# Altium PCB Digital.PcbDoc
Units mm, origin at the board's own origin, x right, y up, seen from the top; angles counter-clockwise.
Board outline 110.7 x 78 mm, 4 copper layers (Top Layer, GND, VCC, Bottom Layer), stack 0.603 mm thick; 50 components, 27 nets, 273 pads, 175 vias.
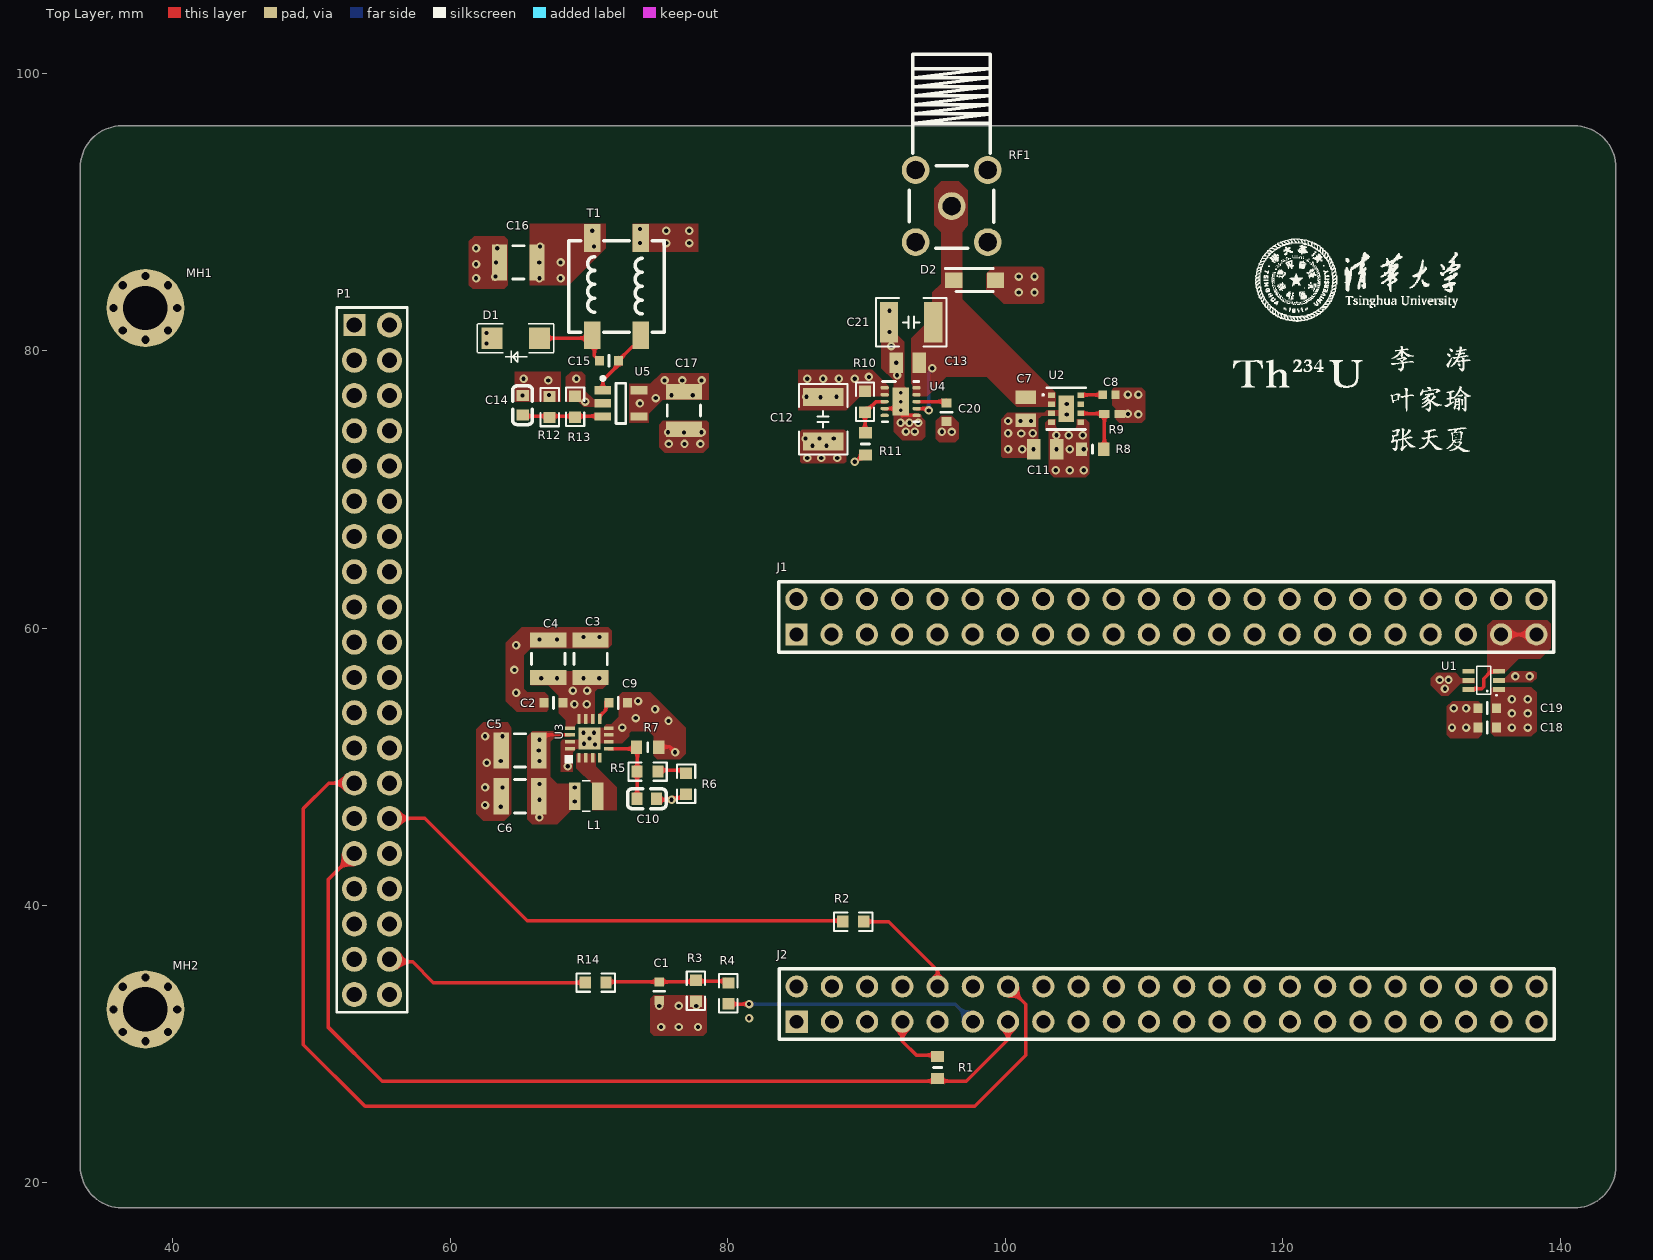
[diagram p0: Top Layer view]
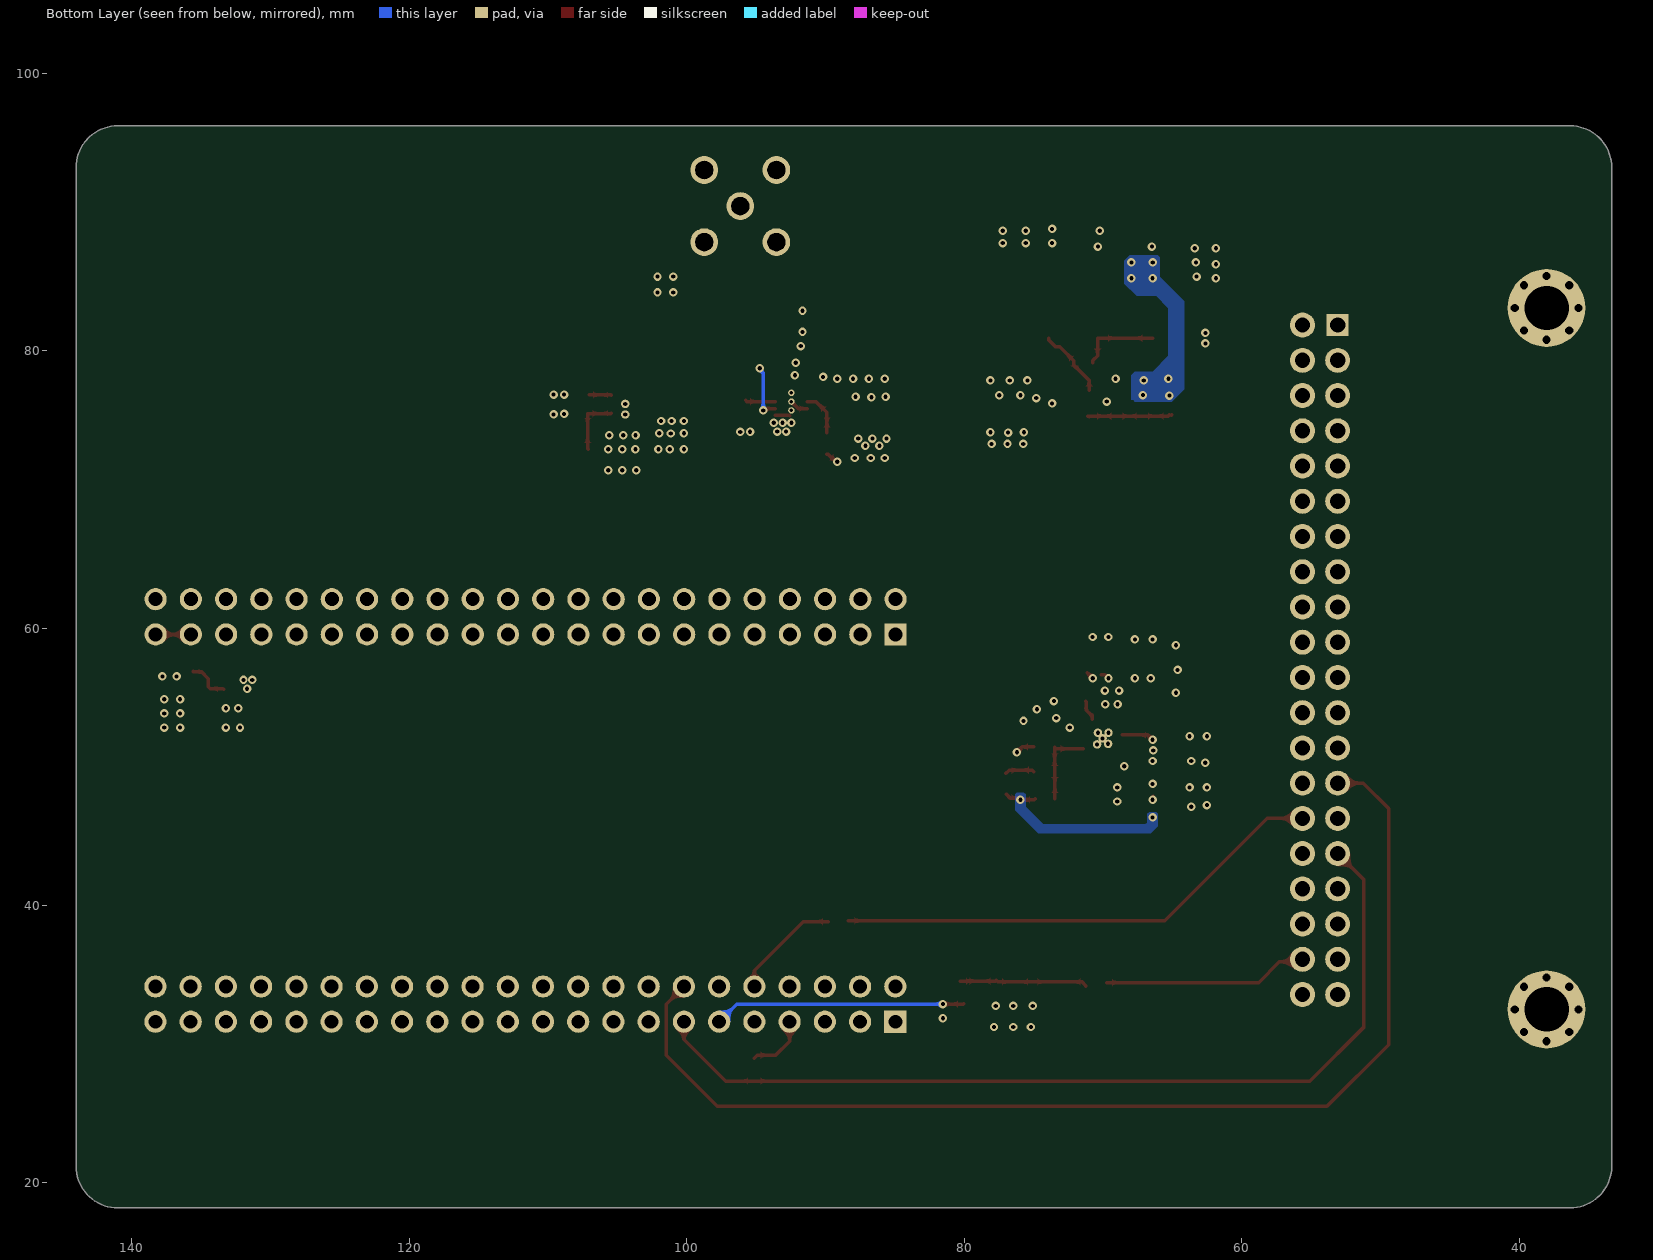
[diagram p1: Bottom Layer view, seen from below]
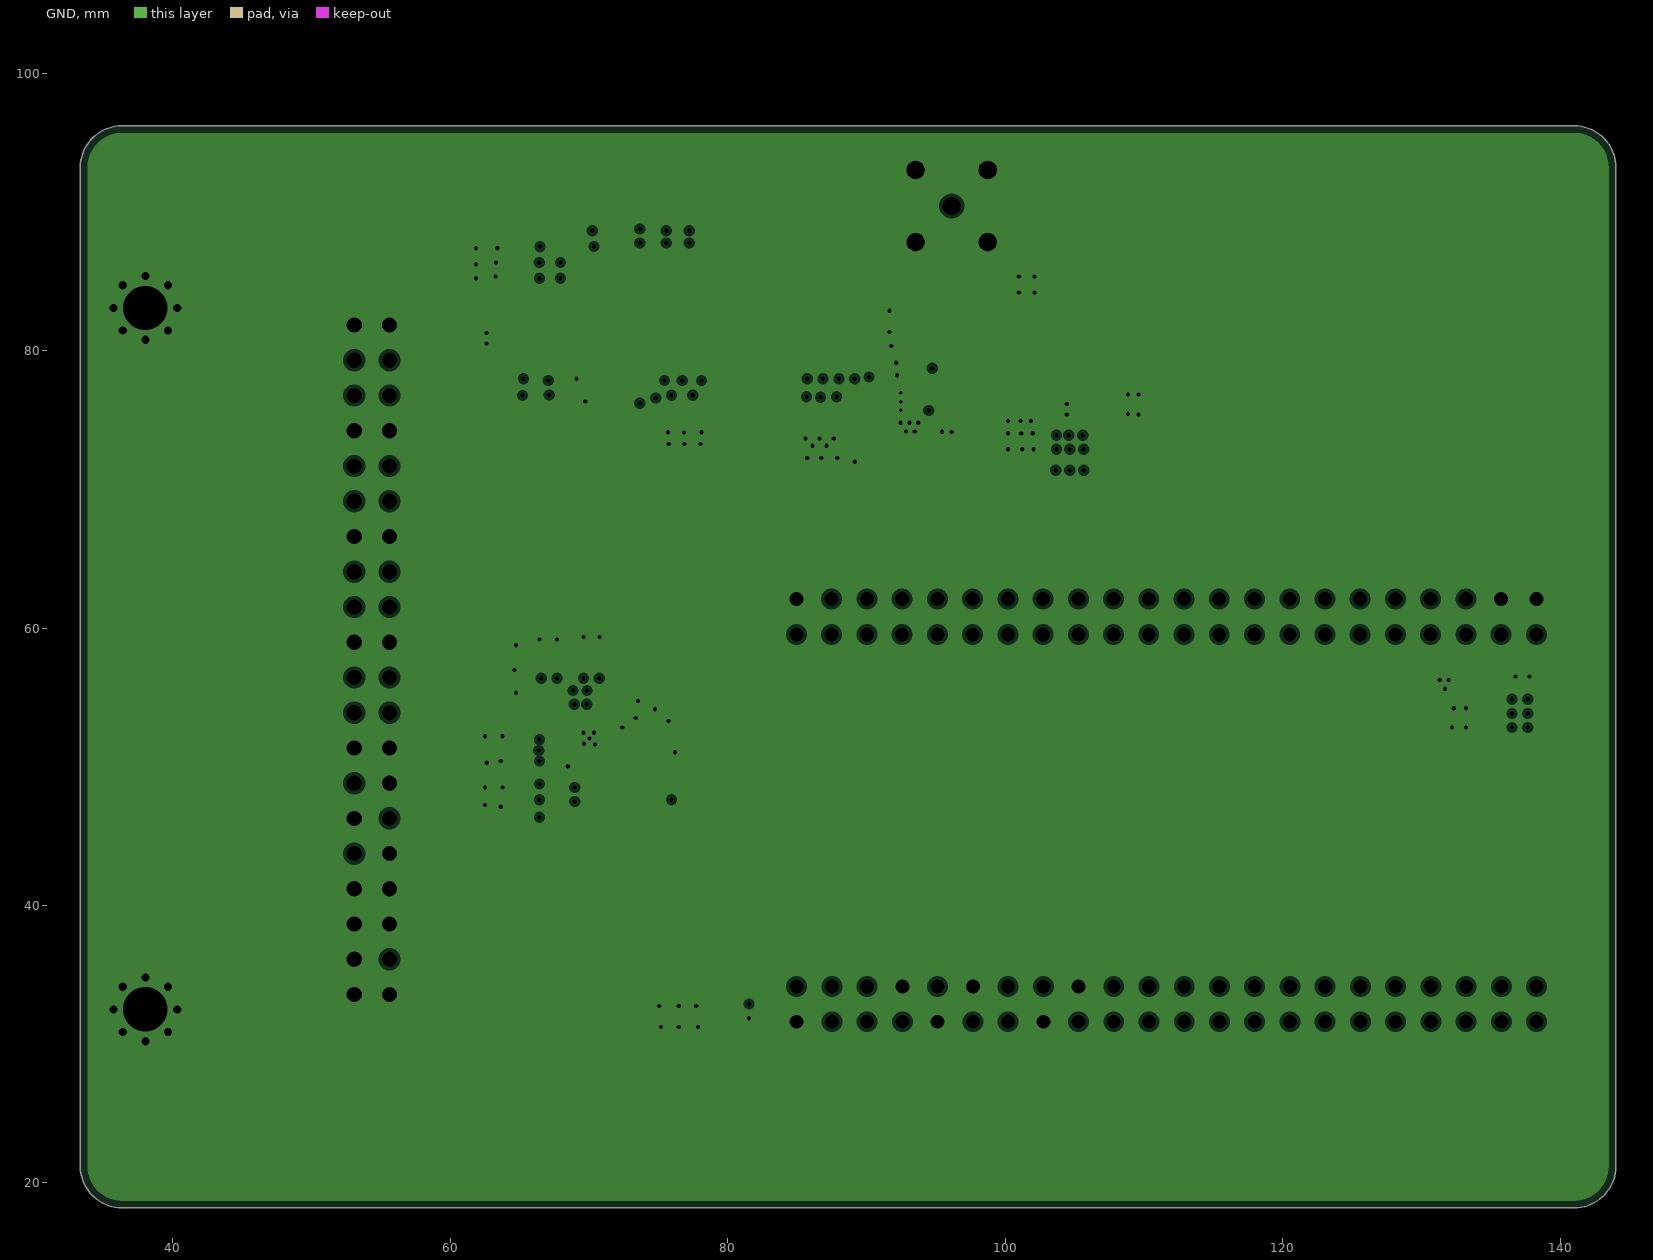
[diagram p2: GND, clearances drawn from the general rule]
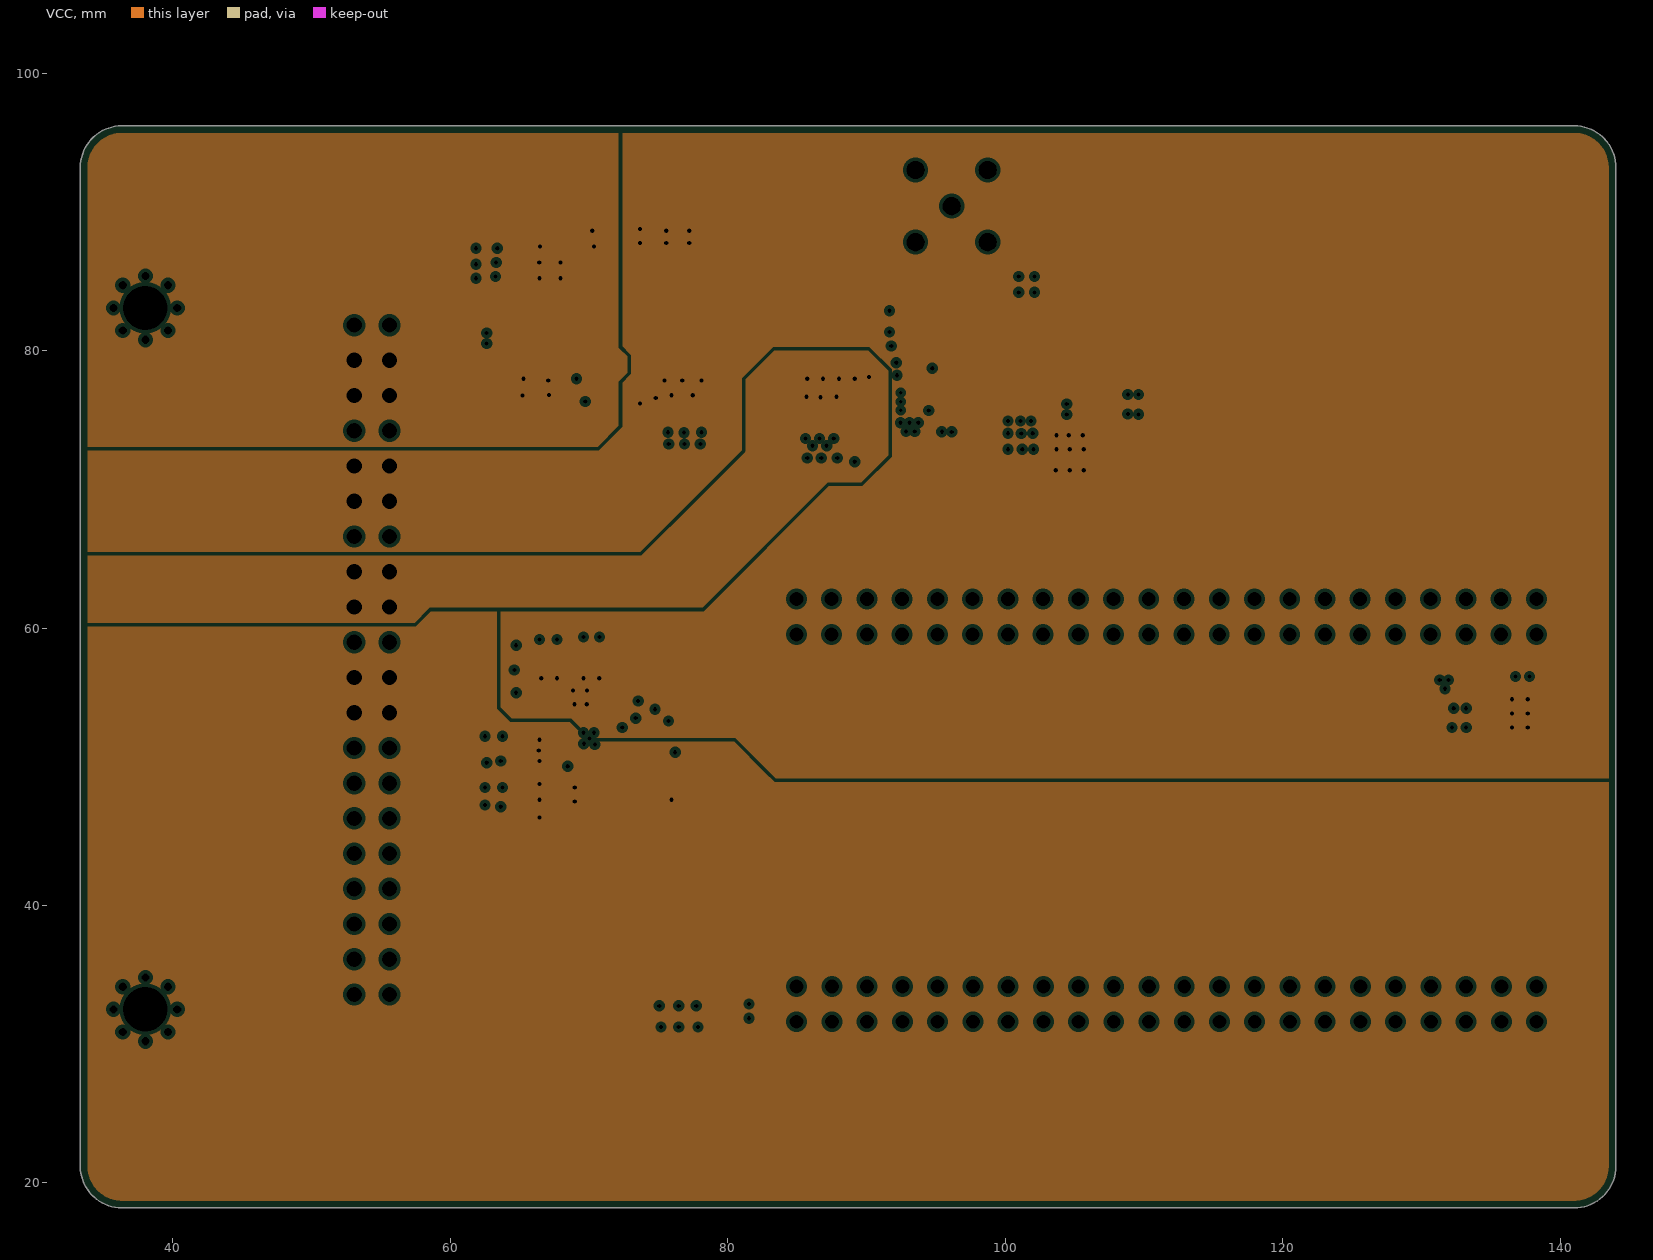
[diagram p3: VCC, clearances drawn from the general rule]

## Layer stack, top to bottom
Top Solder: solder mask 0.0102, Solder Resist, Dk 3.5
Top Layer: signal copper 0.0356
Dielectric 1: dielectric 0.32, FR-4, Dk 4.8
GND: plane copper 0.035, net GND
Dielectric 2: prepreg 0.0711, PP-006, Dk 4.1
VCC: plane copper 0.035, net (Multiple Nets)
Dielectric 3: prepreg 0.0711, PP-006, Dk 4.1
Bottom Layer: signal copper 0.0356
Bottom Solder: solder mask 0.0102, Solder Resist, Dk 3.5

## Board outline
33.322,21.209 33.322,93.209 cw(c36.322,93.209) 36.322,96.209 141.018,96.209 cw(c141.018,93.209) 144.018,93.209 144.018,21.209 cw(c141.018,21.209) 141.018,18.209 36.322,18.209 cw(c36.322,21.209)

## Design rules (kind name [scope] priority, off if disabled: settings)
Clearance [All] p1: gap=0.152 ignorepadtopadclearanceinfootprint=TRUE except(0: Arc-Hole Track-Hole SMDPad-Hole THPad-Hole Via-Hole Fill-Hole Poly-Hole Region-Hole Text-Hole)
HoleSize [All] p1: absolutevalues=TRUE maxlimit=100 minlimit=0.025 maxpercent=80.000 minpercent=20.000
HoleToHoleClearance [All] p1: gap=0 allowstackedmicrovias=TRUE
MinimumSolderMaskSliver [All] p1 off: minsoldermaskwidth=0
PlaneClearance [All] p1: clearance=0.254
PlaneConnect [All] p1: planeconnectstyle=Direct reliefexpansion=0.508 reliefentries=4 reliefconductorwidth=0.254 reliefairgap=0.254
PolygonConnect [All] p1: connectstyle=Direct reliefconductorwidth=0.254 reliefentries=4 polygonreliefangle="90 Angle" airgapwidth=0.254
RoutingVias [All] p1: holewidth=0.305 width=0.61 viastyle="Through Hole" minholewidth=0 minwidth=0 maxholewidth=100 maxwidth=100
SilkToSilkClearance [All] p1 off: silktosilkclearance=0
SilkToSolderMaskClearance [IsPad] p1 off: minsilkscreentomaskgap=0 clearancetoexposedcopper=TRUE
SolderMaskExpansion [All] p1: expansion=0.102 istentingtop=FALSE
Width [All] p1: maxlimit=0.508 minlimit=0.152 preferedwidth=0.254
23 further rules are at their usual default settings.

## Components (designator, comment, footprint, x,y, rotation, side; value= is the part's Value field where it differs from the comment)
C1 "100nF/100V" GRM18x 75.057,33.821 r270 top
C2 "100nF/100V" GRM18x 67.437,54.61 r180 top
C3 "22uF" C1210 70.104,57.785 r270 top
C4 "22uF" C1210 67.056,57.785 r270 top
C5 "22uF" C1210 65.024,51.181 r0 top
C6 "22uF" C1210 65.024,47.879 r0 top
C7 "10uF/25V" CAPC2012X145N 101.473,75.819 r90 top
C8 "3.3nF/50V" CAPC1005X70N 107.49,76.835 r180 top
C9 "10nF/50V" GRM18x 72.096,54.61 r180 top
C10 "1nF" C0603 74.168,47.625 r0 top
C11 "22uF/10V" CAPC2012X145N 102.87,72.898 r0 top
C12 "10uF 50V" C1210-H2r50 86.868,75.057 r90 top
C13 "1uF 100V" CAPC2012X145N 92.964,79.121 r0 top
C14 "220pF" C0603 65.278,76.073 r90 top
C15 "1uF/25V" GRM18x 71.436,79.273 r0 top
C16 "22uF" C1210 64.897,86.36 r0 top
C17 "4.7uF" C1210 76.835,75.692 r90 top
C18 "1uF/25V" GRM18x 134.747,52.832 r180 top
C19 "100nF/100V" GRM18x 134.747,54.229 r180 top
C20 "1uF/25V" GRM18x 95.758,75.565 r90 top
C21 "10uF 50V" C1210-H2r50 93.218,82.042 r0 top
D1 "MBR0520" 1206_Diode 66.421,80.899 r180 top
D2 "TVS/13V" SODFL3616X98N 97.79,85.09 r0 top
J1 "Header_2x22_Female_P2.54" HDR-TH_44P-P2.54-V-F-R2-C22-S2.54 111.617,60.814 r0 top
J2 "Header_2x22_Female_P2.54" HDR-TH_44P-P2.54-V-F-R2-C22-S2.54 111.633,32.893 r0 top
L1 "2.2uH" L1008 69.8,48.073 r180 top
MH1 "Mounting Hole (Screw)" MOUNT_PAD_L 38.015,83.078 r0 top
MH2 "Mounting Hole (Screw)" MOUNT_PAD_L 38.016,32.511 r0 top
P1 "Header_2x20_male_P2.54" 2541WV-2x20P 54.345,57.712 r270 top
R1 "100Ω" RESC1608X55N 95.123,28.321 r270 top
R2 "22Ω" R0603 89.027,38.862 r180 top
R3 "1kΩ" R0603 77.724,33.87 r90 top
R4 "9.1kΩ" R0603 80.01,33.655 r270 top
R5 "301kΩ" R0603 74.224,49.633 r0 top
R6 "11.5kΩ" R0603 76.962,48.768 r270 top
R7 "100kΩ" RESC1608X55N 74.224,51.411 r180 top
R8 "60kΩ" RESC1608X55N 106.299,72.898 r180 top
R9 "12kΩ" RESC1005X35N 107.696,75.438 r180 top
R10 "10.5kΩ" R0603 89.916,76.327 r90 top
R11 "2kΩ" RESC1608X55N 89.916,73.279 r90 top
R12 "29.4kΩ" R0603 67.183,75.946 r90 top
R13 "10kΩ" R0603 68.961,75.946 r270 top
R14 "0Ω" R0603 70.485,34.417 r0 top
RF1 "HJ-SMA508" HJ-SMA508 100.776,93.277 r270 top
T1 "CLS62NP-100NC" SMD-4P,6.8x6.6mm 71.755,84.582 r90 top
U1 "lm66100dckr_c2869734" SC-70-6_L2.0-W1.3-P0.65-LS2.1-BL 134.493,56.234 r90 top
U2 "TPS82130SILR" SIL0008D 104.394,75.819 r0 top
U3 "TPS62130RGT" QFN16 70.021,52.046 r90 top
U4 "TPS7A90" DSK0010A 92.456,76.327 r0 top value=Value
U5 "LT1931" SOT23-5 72.293,76.2 r0 top value=Value

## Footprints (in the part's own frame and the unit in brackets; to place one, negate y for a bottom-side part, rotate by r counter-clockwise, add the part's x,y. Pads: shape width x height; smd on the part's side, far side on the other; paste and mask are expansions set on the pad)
1206_Diode [mil] "1206_Diode"
  rect 60x60 smd: 1(0,0) 2(135,0)
  silkscreen extent -41,-41 176,70, body extent -11,-34 141,33, height 56
2541WV-2x20P [mil]
  rect 62x62 hole 43.3: 1(-950,-50)
  round 70.9 hole 43.3: 2(-950,50) 3(-850,-50) 4(-850,50) 5(-750,-50) 6(-750,50) 7(-650,-50) 8(-650,50) 9(-550,-50) 10(-550,50) 11(-450,-50) 12(-450,50) 13(-350,-50) 14(-350,50) 15(-250,-50) 16(-250,50) 17(-150,-50) 18(-150,50) 19(-50,-50) 20(-50,50) 21(50,-50) 22(50,50) 23(150,-50) 24(150,50) 25(250,-50) 26(250,50) 27(350,-50) 28(350,50) 29(450,-50) 30(450,50) 31(550,-50) 32(550,50) 33(650,-50) 34(650,50) 35(750,-50) 36(750,50) 37(850,-50) 38(850,50) 39(950,-50) 40(950,50)
  silkscreen extent -1000,-100 1000,100
C0603 [mm]
  rect 0.8x0.9 smd paste+0.051: 1(-0.707,0.075) 2(0.693,0.075)
  silkscreen extent -1.4,-0.64 1.38,0.79
C1210 [mm] "Chip Capacitor, Body 3.2x2.5mm, IPC High Density"
  rect 1.1x2.6 smd: 1(-1.35,0) 2(1.35,0)
  silkscreen extent -0.4,-1.2 0.4,1.2, body extent -1.7,-1.35 1.7,1.35, height 1.3
C1210-H2r50 [mm]
  rect 1.321x2.921 smd paste+0 mask+0.076: 1(-1.6,0) 2(1.6,0)
  silkscreen extent -2.55,-1.75 2.55,1.75, body extent -1.6,-1.27 1.6,1.23, height 2.6
CAPC1005X70N [mm]
  rect 0.6x0.62 smd: 1(-0.46,0) 2(0.46,0)
  body extent -0.5,-0.25 0.5,0.25, height 0.5
CAPC2012X145N [mm]
  rect 0.97x1.47 smd: 1(-0.83,0) 2(0.83,0)
  body extent -1,-0.63 1,0.63, height 1.45
DSK0010A [mm]
  oval 0.6x0.25 smd paste+0 mask+0: 1(-1.15,1) 2(-1.15,0.5) 3(-1.15,0) 4(-1.15,-0.5) 5(-1.15,-1) 6(1.15,-1) 7(1.15,-0.5) 8(1.15,0) 9(1.15,0.5) 10(1.15,1)
  round 0.457 hole 0.254: 11(0,-0.635) 11(0,0) 11(0,0.635)
  rect 1.2x2 smd paste-0.6 mask+0: 11(0,0)
  silkscreen extent -1.3,-1.45 1.3,1.45
GRM18x [mm]
  rect 0.65x0.7 smd: 1(-0.675,0) 2(0.675,0)
  silkscreen extent 0,-0.4 0,0.4, body extent -0.8,-0.45 0.8,0.45, height 0.8
HDR-TH_44P-P2.54-V-F-R2-C22-S2.54 [mil]
  rect 63x63 hole 39.4: 1(-1050,-50)
  round 63 hole 39.4: 2(-1050,50) 3(-950,-50) 4(-950,50) 5(-850,-50) 6(-850,50) 7(-750,-50) 8(-750,50) 9(-650,-50) 10(-650,50) 11(-550,-50) 12(-550,50) 13(-450,-50) 14(-450,50) 15(-350,-50) 16(-350,50) 17(-250,-50) 18(-250,50) 19(-150,-50) 20(-150,50) 21(-50,-50) 22(-50,50) 23(50,-50) 24(50,50) 25(150,-50) 26(150,50) 27(250,-50) 28(250,50) 29(350,-50) 30(350,50) 31(450,-50) 32(450,50) 33(550,-50) 34(550,50) 35(650,-50) 36(650,50) 37(750,-50) 38(750,50) 39(850,-50) 40(850,50) 41(950,-50) 42(950,50) 43(1050,-50) 44(1050,50)
  silkscreen extent -1100,-100 1100,100
HJ-SMA508 [mm]
  round 2 hole 1.3 slot 1.305 at 0 deg paste-2539.97 mask+0.051: 1(2.853,-4.637) 2(0.253,-2.037) 3(0.253,-7.237) 4(5.453,-7.237) 5(5.453,-2.037)
  silkscreen extent -8.1,-7.69 5.9,-1.59
L1008 [mm]
  rect 0.85x2 smd: 1(-0.821,0.194) 2(0.839,0.194)
  silkscreen extent -0.28,-0.91 0.3,1.29
MOUNT_PAD_L [mm]
  round 5.6 hole 3.2: 1(0,0)
QFN16 [mm]
  rect 1.6x1.6 smd: 0(0,0)
  rect 0.7x0.25 smd: 1(-1.4,0.75) 2(-1.4,0.25) 3(-1.4,-0.25) 4(-1.4,-0.75) 9(1.4,-0.75) 10(1.4,-0.25) 11(1.4,0.25) 12(1.4,0.75)
  rect 0.25x0.7 smd: 5(-0.75,-1.4) 6(-0.25,-1.4) 7(0.25,-1.4) 8(0.75,-1.4) 13(0.75,1.4) 14(0.25,1.4) 15(-0.25,1.4) 16(-0.75,1.4)
  silkscreen extent -1.8,1.2 -1.2,1.8, body extent -1.5,-1.5 1.5,1.5, height 0.9
R0603 [mm]
  rect 0.806x0.864 smd paste-100 mask+0.051: 1(-0.765,0.026) 2(0.741,0.026)
  silkscreen extent -1.4,-0.64 1.37,0.69
RESC1005X35N [mm]
  rect 0.75x0.6 smd: 1(-0.55,0) 2(0.55,0)
  body extent -0.5,-0.25 0.5,0.25, height 0.35
RESC1608X55N [mm]
  rect 0.8x0.95 smd: 1(-0.8,0) 2(0.8,0)
  silkscreen extent 0,-0.3 0,0.3, body extent -0.8,-0.4 0.8,0.4, height 0.55
SC-70-6_L2.0-W1.3-P0.65-LS2.1-BL [mil]
  rect 13.8x33.5 smd paste+0 mask+2: 1(-25.6,-43.3) 2(0,-43.3) 3(25.6,-43.3) 4(25.6,43.3) 5(0,43.3) 6(-25.6,43.3)
  silkscreen extent -44,-38 39,20
SIL0008D [mm]
  rect 0.5x0.4 smd: 1(-1.05,0.975) 2(-1.05,0.325) 3(-1.05,-0.325) 4(-1.05,-0.975) 5(1.05,-0.975) 6(1.05,-0.325) 7(1.05,0.325) 8(1.05,0.975)
  rect 1.1x1.9 smd: 9(0,0)
  silkscreen extent -1.7,-1.5 1.4,1.5, body extent -1.4,-1.5 1.4,1.5, height 1.31
SMD-4P,6.8x6.6mm [mm]
  rect 2x1.2 smd paste+0 mask+0.05: 1(-3.468,1.532) 2(-3.468,-1.968) 3(3.532,-1.968) 4(3.532,1.532)
  silkscreen extent -3.27,-3.65 3.33,3.21
SODFL3616X98N [mm]
  rect 1.24x1.12 smd: 1(-1.5,0) 2(1.5,0)
  silkscreen extent -2.12,-0.82 1.35,0.82, body extent -1.8,-0.82 1.8,0.82, height 0.98
SOT23-5 [mm] "SOT23, for LT1964, 5-Leads, Body 2.9x2.8mm (max), Pitch 0.95mm, IPC Medium Density"
  rect 1.2x0.6 smd: 1(-1.3,0.95) 2(-1.3,0) 3(-1.3,-0.95) 4(1.3,-0.95) 5(1.3,0.95)
  silkscreen extent -1.42,-1.45 0.35,1.92, body extent -1.37,-1.46 0.97,1.46, height 1

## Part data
C1 C2 C19: library part GCM188R72A104KA64D, "100nF 10% 100V X7R 0603", Arrow Part Number=GRM188Z71A106KA73D, Manufacturer_Name="Murata Electronics", Mouser Part Number=81-GRM188Z71A106KA3D
C3 C4 C5 C6 C16: library part GRM32ER71E226KE15L, "22uF ±10% 25V 1210 X7R"
C7: library part GCM21BC71E106KE36L, "10uF 10% 25V X7S 0805 汽车级", Arrow Part Number=GRM21BR72A103KA01L, Manufacturer_Name="Murata Electronics", Mouser Part Number=81-GRM21BR72A103K
C8: library part GRM1555C1H332JE01D, "3.3nF 5% 50V 0402 NP0", Manufacturer_Name="Murata Electronics", Manufacturer_Part_Number=GRM155C71H683KE19D, Mouser Part Number=81-GRM155C71H683KE9D
C9: library part GCM1885C1H103GA16D, "10nF 2% 50V 0603 C0G", Manufacturer_Name="Murata Electronics", Manufacturer_Part_Number=GRM155C71H683KE19D, Mouser Part Number=81-GRM155C71H683KE9D
C10: library part GRM188R71H102KA01D, "1nF ±10% 50V 0603 X7R"
C11: library part GRM21BZ71A226ME15L, "22uF 10% 10V X7R 0805", Arrow Part Number=GRM21BR72A103KA01L, Manufacturer_Name="Murata Electronics", Mouser Part Number=81-GRM21BR72A103K
C12 C21: library part GRM32ER71H106KA12L, "10uF 50V 10% 1210 X7R"
C13: library part GCM21BC72A105KE36L, "1uF 10% 100V X7S 0805", Arrow Part Number=GRM21BR72A103KA01L, Manufacturer_Name="Murata Electronics", Mouser Part Number=81-GRM21BR72A103K
C14: library part GCM1885C2A221FA16D, "220pF ±1% 100V 0603 C0G"
C15 C18 C20: library part GCM188R71E105KA64D, "1uF 10% 25V X7R 0603", Arrow Part Number=GRM188Z71A106KA73D, Manufacturer_Name="Murata Electronics", Mouser Part Number=81-GRM188Z71A106KA3D
C17: library part GRM32ER71H475KA88L, "4.7uF ±10% 50V X7R 1210"
D1: library part DIODE
D2: library part SMF13A, "TVS 工作电压13V 最大钳位电压21.5V 单向", Arrow Part Number=SMF26AT1G, Manufacturer_Name=LITTELFUSE
J1 J2: "插孔结构:2x22P;间距:2.54mm;行距:2.54mm;圆孔/方孔:方孔;安装方式:直插;排数:双排;总孔位数:44P;额定电流:3A;额定电压:-;插孔方向:顶部;塑高:8.5mm;触头材质:黄铜;触头镀层:金;工作温度:-40℃~+105℃;", Current Rating=3A, JLCPCB Part Class="Extended Part", LCSC Part Name="间距2.54mm 2x22Pin 直插 PC3.0 H8.5", Manufacturer=HC(虹成电子), ManufacturerPart=HC-PM254-8.5H-2x22PZ, Operating Temperature=-40℃~+105℃, Voltage Rating (Max)=-
L1: library part FXLB252012-2R2-M, "2.2uH ±20% 3.3A 1008"
MH1 MH2: library part Mounting-Hole-Screw_1, "Mounting Hole, M3 Screw"
P1: "插针结构:2x20P;间距:2.54mm;行距:2.54mm;圆针/方针:方针;安装方式:直插;排数:双排;总PIN位数:40P;额定电流:3A;配合针长度:6mm;塑高:2.54mm;端接针长度:3mm;触头材质:黄铜;触头镀层:金;工作温度:-55℃~+105℃;", Current Rating=3A, JLCPCB Part Class="Extended Part", LCSC Part Name="2x20P 间距:2.54mm 方针 直插", Manufacturer=HanElectricity(瀚源), ManufacturerPart=2541WV-2x20P, Operating Temperature=-55℃~+105℃
R1: library part SR0603FR-7T100RL, "100Ω 1% 0603 250mW 厚膜 耐浪涌", Manufacturer_Name=YAGEO, Manufacturer_Part_Number=RT0603BRD07523KL
R2: library part RT0603BRE0722RL, "薄膜电阻 22Ω ±0.1% 100mW 0603"
R3: library part RT0603BRE071KL, "薄膜电阻 1kΩ ±0.1% 100mW 0603"
R4: library part RT0603BRE079K1L, "薄膜电阻 9.1kΩ ±0.1% 100mW 0603"
R5: library part RT0603BRD07301KL, "薄膜电阻 301kΩ ±0.1% 100mW 0603"
R6: library part RT0603BRD0711K5L, "薄膜电阻 11.5kΩ ±0.1% 100mW 0603"
R7 R8: library part RT0603BRD07100KL, "100kΩ 0.1% 0603 100mW 薄膜 25ppm/℃", Manufacturer_Name=YAGEO, Manufacturer_Part_Number=RT0603BRD07523KL
R9: library part RT0402BRD0720KL, "20kΩ 0.1% 0402 62.5mW 薄膜 25ppm/℃", Manufacturer_Name=YAGEO, Manufacturer_Part_Number=RT0402BRD07100RL, Mouser Part Number=603-RT0402BRD07100RL
R10: library part RT0603BRD0710K5L, "薄膜电阻 10.5kΩ ±0.1% 100mW 0603"
R11: library part RT0603BRD072KL, "2kΩ 0.1% 0603 100mW 薄膜 25ppm/℃", Manufacturer_Name=YAGEO, Manufacturer_Part_Number=RT0603BRD07523KL
R12: library part RT0603BRD0729K4L, "薄膜电阻 29.4kΩ ±0.1% 100mW 0603"
R13: library part RT0603BRD0710KL, "薄膜电阻 10kΩ ±0.1% 100mW 0603"
R14: library part PMR03EZPJ000, "厚膜电阻 0Ω 250mW 0603"
T1: "10uH ±30% SMD-4P,6.8x6.6mm"
U1: "LM66100 具有集成式 FET 的 1.5V 至 5.5V、1.5A、0.5μA IQ 理想二极管", Continuous Current (Imax)=1.5A, Gate Drive Voltage=-, Input Voltage (Vin)=1.5V~5.5V, JLCPCB Part Class="Extended Part", LCSC Part Name="5.5-V, 1.5-A 79-mΩ, 低静态电流理想二极管，带输入极性保护", Manufacturer=TI(德州仪器), ManufacturerPart=LM66100DCKR, Operating Temperature=-40℃~+125℃, Quiescent Current=150nA
U2: "内置电感的宽输入降压DCDC，工作频率2MHz", Manufacturer_Name="Texas Instruments", Mouser Part Number=595-TPS82130SILR
U4: library part TPS7A9001DSKR, "Imported", Manufacturer="Texas Instruments"
U5: library part LT1931AIS5, "Imported", Manufacturer_Part_Number=lt1931ais5

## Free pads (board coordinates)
  round 0.61 hole 0.305: 2(69.596,52.451) 2(69.623,51.655) 2(70.021,52.046) 2(70.358,52.451) 2(70.416,51.615) 2(104.43,75.398) 2(104.43,76.16)

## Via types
v1: diameter 0.61, hole 0.305, Top Layer to Bottom Layer, 159 vias
v2: diameter 1, hole 0.6, Top Layer to Bottom Layer, 16 vias

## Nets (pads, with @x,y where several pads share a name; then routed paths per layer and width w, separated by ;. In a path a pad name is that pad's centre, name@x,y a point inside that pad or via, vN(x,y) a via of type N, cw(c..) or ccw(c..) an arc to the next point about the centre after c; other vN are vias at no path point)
"3.3V SS": C9.2 U3.9 | length 1.5
  Top Layer w0.254: U3.9 70.771,53.667 71.192,54.088 71.192,54.682 C9.2@71.247,54.737
+3V3: C5.2 C6.2 C10.2 L1.2 P1.21 P1.22 P1.23 P1.24 R6.2 U3.14 | length 5.1
  Top Layer w0.254: C6.2 66.421,47.832 v1(66.421,47.625) ; v1(66.421,51.943) 66.774,52.296 U3.14 ; L1.2@68.961,48.324 v1(68.961,48.514) ; C10.2 74.936,47.625 v1(75.946,47.625) 76.042,47.625 76.168,47.75 76.694,47.75 R6.2@76.979,48.035
  other v1: 66.421,46.355 68.961,47.498 66.421,48.768 66.421,50.419 66.374,51.181
+5V: C2.1 C3.2 C4.2 C11.2 C17.2 C18.1 C19.1 P1.9 P1.10 P1.11 P1.12 R8.2 T1.3 U1.1 U2.4 U2.5 U3.10 U3.11 U3.12 U3.13 U5.4 U5.5 | length 1.2
  Top Layer w0.254: v1(69.596,56.388) 69.85,56.642 C3.2@70.129,56.642 ; v1(70.739,56.388) C3.2@71.12,56.769
  other v1: 136.525,52.832 137.668,52.832 136.525,53.848 137.668,53.848 68.938,54.506 69.827,54.506 136.525,54.864 137.668,54.864 68.834,55.499 69.85,55.499 66.548,56.388 67.691,56.388 103.632,71.374 104.648,71.374 105.664,71.374 103.7,72.898 104.648,72.898 105.664,72.898 103.686,73.902 104.575,73.902 105.591,73.902 73.66,76.2 74.803,76.581 75.946,76.784 77.47,76.784 75.438,77.851 76.708,77.851 78.105,77.851 73.66,87.757 75.565,87.757 77.216,87.757 75.565,88.646 77.216,88.646 73.66,88.773
+5VA: C12.2 P1.15 P1.16 P1.17 P1.18 R10.2 U4.1 U4.2
  other v1: 86.685,76.634 85.669,76.685 87.828,76.685 85.725,77.978 86.868,77.978 88.011,77.978 89.154,77.978 90.17,78.105
+6V: C7.2 C13.2 C21.2 D2.1 RF1.1 U2.1 U2.2 U4.7 U4.9 U4.10 | length 4.1
  Top Layer w0.254: U4.7 94.257,75.827 94.392,75.692 v1(94.488,75.692)
  Bottom Layer w0.254: v1(94.488,75.692) 94.488,78.39 94.742,78.644 v1(94.742,78.74)
-5VA: C14.2 C16.2 P1.3 P1.4 P1.5 P1.6 R12.2 T1.4
  other v1: 65.203,76.766 67.117,76.797 67.056,77.851 65.278,77.978 66.421,85.217 67.945,85.217 66.413,86.357 67.945,86.36 66.464,87.5 70.358,87.503 70.231,88.646
ADC_BUSY_IRQ: J2.7 R1.1 | length 4.4
  Top Layer w0.254: J2.7 92.583,30.226 93.599,29.21 94.908,29.21 R1.1@95.123,28.995
ADC_SCK: J2.14 P1.27 | length 82.4
  Top Layer w0.254: P1.27 51.235,48.822 49.403,46.99 49.403,29.972 53.848,25.527 97.79,25.527 101.473,29.21 101.473,32.893 J2.14
ADC_SDO: J2.13 P1.31 R1.2 | length 66.4
  Top Layer w0.254: P1.31 51.181,41.848 51.181,31.242 55.079,27.344 95.123,27.344 97.194,27.344 100.203,30.353 J2.13
"FB 3.3V": C10.1 R5.1 R7.2 U3.5 | length 5.8
  Top Layer w0.254: U3.5 73.359,51.296 73.474,51.411 R5.1@73.474,49.659 ; R5.1 73.458,47.703 C10.1
GND: C1.2 C2.2 C3.1 C4.1 C5.1 C6.1 C7.1 C8.1 C9.1 C11.1 C12.1 C13.1 C16.1 C17.1 C18.2 C19.2 C20.1 C21.1 D1.2 D2.2 J1.2 J1.42 J1.44 J2.1 J2.8 J2.9 J2.12 J2.15 J2.18 MH1.1 MH2.1 P1.1 P1.2 P1.7 P1.8 P1.13 P1.14 P1.19 P1.20 P1.25 P1.26 P1.28 P1.29 P1.32 P1.33 P1.34 P1.35 P1.36 P1.37 P1.39 P1.40 pad.2 R3.1 R7.1 R9.1 R11.1 R13.1 RF1.2 RF1.3 RF1.4 RF1.5 U1.2 U1.5 U2.3 U2.9 U3.0 U3.6 U3.7 U3.8 U3.15 U3.16 U4.4 U4.6 U4.11 U5.2 | length 4.7
  Top Layer w0.254: R7.1@74.997,51.435 75.805,51.435 76.186,51.054 v1(76.2,51.054) ; v1(89.154,71.997) 89.25,71.997 89.445,72.192 89.479,72.192 89.816,72.529 R11.1@89.916,72.529 ; U4.4 91.956,75.827 U4.11@92.456,76.327 ; 92.583,75.311 92.599,75.327 U4.6
  other v1: 75.184,31.242 76.454,31.242 77.851,31.242 81.534,31.877 75.057,32.766 76.454,32.766 77.724,32.766 63.627,47.117 62.496,47.243 62.496,48.513 63.754,48.514 68.453,50.038 62.623,50.291 63.627,50.419 62.496,52.196 63.754,52.197 72.39,52.832 132.207,52.832 133.223,52.832 75.724,53.305 73.36,53.509 74.757,54.144 132.334,54.229 133.223,54.229 73.533,54.737 64.738,55.336 131.699,55.626 131.318,56.261 131.953,56.261 136.779,56.515 137.795,56.515 64.611,56.987 64.738,58.765 66.421,59.182 67.691,59.182 69.603,59.358 70.746,59.358 85.725,72.263 86.741,72.263 87.884,72.263 100.203,72.898 101.219,72.898 102.04,72.898 86.106,73.152 87.122,73.152 75.735,73.276 76.878,73.276 78.021,73.276 85.598,73.66 86.614,73.66 87.63,73.66 100.203,74.041 101.146,74.029 101.981,74.041 76.835,74.092 75.692,74.117 78.105,74.117 96.143,74.145 92.837,74.168 93.472,74.168 95.431,74.156 92.456,74.803 93.091,74.803 93.726,74.803 100.203,74.93 101.092,74.93 101.854,74.93 109.602,75.407 108.839,75.438 69.723,76.327 108.839,76.835 109.601,76.835 69.088,77.978 92.202,78.232 92.134,79.121 91.781,80.333 62.611,80.518 62.611,81.28 91.654,81.349 91.654,82.873 100.965,84.201 102.108,84.201 61.849,85.217 63.246,85.344 100.965,85.344 102.108,85.344 61.849,86.233 63.297,86.36 61.849,87.376 63.373,87.376
  other v2: 38.016,30.211 36.39,30.884 39.642,30.884 35.716,32.511 40.316,32.511 36.39,34.137 39.642,34.137 38.016,34.811 38.015,80.778 36.389,81.452 39.642,81.452 35.715,83.078 40.315,83.078 36.389,84.704 39.642,84.704 38.015,85.378
NetC1_1: C1.1 R3.2 R4.1 R14.2 | length 9.3
  Top Layer w0.254: R14.2@71.226,34.189 71.226,34.217 71.505,34.496 C1.1 77.583,34.496 R3.2 77.763,34.547 R4.1@80.29,34.547
NetC8_2: C8.2 U2.8 | length 1.6
  Top Layer w0.254: U2.8 105.465,76.814 107.01,76.814 C8.2
NetC14_1: C14.1 R12.1 R13.2 U5.3 | length 9.7
  Top Layer w0.254: C14.1@65.04,75.366 C14.1@65.071,75.335 ; C14.1 65.288,75.28 R12.1@67.157,75.28 ; R13.2@68.86,75.28 R12.1@67.157,75.28 ; U5.3 70.963,75.28 R13.2@68.987,75.28 ; U5.3@71.09,75.28 R13.2@68.987,75.28 ; R12.1@67.157,75.28 R13.2@68.987,75.28
NetC15_1: C15.1 D1.1 T1.1 | length 5.9
  Top Layer w0.254: D1.1 70.381,80.899 70.383,80.901 70.383,79.643 70.739,79.287 C15.1@70.739,79.121
NetC15_2: C15.2 T1.2 U5.1 | length 5.1
  Top Layer w0.254: U5.1 70.993,77.851 72.111,78.969 72.111,79.121 C15.2 73.115,80.278 73.416,80.278 73.889,80.751 T1.2@73.889,80.901
NetC20_2: C20.2 U4.8 | length 2.2
  Top Layer w0.254: U4.8 93.608,76.329 95.658,76.329 C20.2@95.758,76.429
NetR5_2: R5.2 R6.1 | length 2.2
  Top Layer w0.254: R5.2@74.974,49.633 75.101,49.76 76.761,49.76 R6.1
NetR8_1: R8.1 R9.2 U2.6 | length 4.3
  Top Layer w0.254: U2.6 105.472,75.466 107.118,75.466 R9.2 107.146,72.945 R8.1
NetR10_1: R10.1 R11.2 U4.3 | length 3.2
  Top Layer w0.254: R11.2@89.916,74.091 89.89,74.117 R10.1 89.919,75.562 90.682,76.325 91.304,76.325 U4.3
"PG 3.3V": U3.4
PH_RESTART: J2.10 R2.1 | length 7.9
  Top Layer w0.254: R2.1 91.593,38.836 95.123,35.306 J2.10
Restart: P1.30 R2.2 | length 35.8
  Top Layer w0.254: P1.30 58.155,46.282 65.535,38.901 R2.2@88.366,38.901
"SW 3.3V": L1.1 U3.1 U3.2 U3.3
Threshold: P1.38 R14.1 | length 14.8
  Top Layer w0.254: P1.38 55.795,35.941 57.277,35.941 58.775,34.443 R14.1
THRESHOLD_DAC: J2.11 R4.2 | length 18.2
  Top Layer w0.254: R4.2 80.056,32.893 v1(81.534,32.893)
  Bottom Layer w0.254: v1(81.534,32.893) 96.393,32.893 J2.11
USB_5V: J1.41 J1.43 U1.3 U1.6 | length 5.6
  Top Layer w0.254: U1.6 133.441,55.632 134.344,55.632 134.493,55.78 134.493,56.361 134.968,56.836 135.545,56.836 U1.3 ; J1.41@135.763,59.536 J1.43@138.303,59.536
pads on no net: J1.1 J1.3 J1.4 J1.5 J1.6 J1.7 J1.8 J1.9 J1.10 J1.11 J1.12 J1.13 J1.14 J1.15 J1.16 J1.17 J1.18 J1.19 J1.20 J1.21 J1.22 J1.23 J1.24 J1.25 J1.26 J1.27 J1.28 J1.29 J1.30 J1.31 J1.32 J1.33 J1.34 J1.35 J1.36 J1.37 J1.38 J1.39 J1.40 J2.2 J2.3 J2.4 J2.5 J2.6 J2.16 J2.17 J2.19 J2.20 J2.21 J2.22 J2.23 J2.24 J2.25 J2.26 J2.27 J2.28 J2.29 J2.30 J2.31 J2.32 J2.33 J2.34 J2.35 J2.36 J2.37 J2.38 J2.39 J2.40 J2.41 J2.42 J2.43 J2.44 U1.4 U2.7 U4.5

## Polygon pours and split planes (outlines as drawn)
"SW 3.3V" on Top Layer "GND_bottom" (solid, pour order 13): 69.088,50.927 70.485,50.927 70.485,50.038 72.009,48.514 72.009,46.863 70.231,46.863 70.231,48.768 69.088,49.911
GND on Top Layer "GND_L01_P084" (solid, remove dead copper, pour order 84): 72.136,54.673 72.136,53.594 71.501,52.959 72.136,52.324 72.136,52.261 72.707,52.26 73.025,52.578 74.295,52.578 74.676,52.197 74.676,50.8 74.93,50.546 76.581,50.546 76.962,50.927 76.962,52.832 74.422,55.372 73.406,55.372
GND on Top Layer "GND_L01_P082" (solid, remove dead copper, pour order 82): 70.612,52.832 72.136,52.832 72.136,51.689 70.739,51.689
+3V3 on Top Layer "+3V3_L01_P051" (solid, remove dead copper, pour order 51): 67.697,52.296 67.415,52.578 65.913,52.578 65.532,52.197 65.532,46.228 65.913,45.847 67.691,45.847 68.834,46.99 69.088,46.99 69.342,47.244 69.342,48.514 69.088,48.768 67.691,48.768 67.183,49.276 67.183,51.816
GND on Top Layer "GND_L01_P081" (solid, remove dead copper, pour order 81): 85.344,74.295 85.217,74.168 85.217,72.009 85.344,71.882 88.392,71.882 88.519,72.009 88.519,74.168 88.392,74.295
GND on Top Layer "GND_L01_P080" (solid, remove dead copper, pour order 80): 92.964,77.216 92.71,77.47 92.71,80.645 91.821,81.534 91.059,80.772 91.059,78.74 91.948,77.851 91.948,77.216
USB_5V on Top Layer "USB_5V_L01_P079" (solid, remove dead copper, pour order 79): 134.747,56.615 134.747,60.198 135.128,60.579 139.065,60.579 139.319,60.325 139.319,58.547 138.557,57.785 137.033,57.785 136.017,56.769 135.95,56.836 134.968,56.836
GND on Top Layer "GND_L01_P078" (solid, remove dead copper, pour order 78): 95.377,75.311 94.996,74.93 94.996,73.66 95.25,73.406 96.393,73.406 96.647,73.66 96.647,74.803 96.139,75.311
GND on Top Layer "GND_L01_P077" (solid, remove dead copper, pour order 77): 91.956,75.827 91.948,75.819 91.948,74.168 92.583,73.533 93.98,73.533 94.234,73.787 94.234,74.93 93.98,75.184 93.98,75.311 93.853,75.438 92.964,75.438
+5V on Top Layer "+5V_L01_P074" (solid, remove dead copper, pour order 74): 103.124,75.057 102.87,74.803 102.87,74.422 103.124,74.168 103.124,71.247 103.505,70.866 105.791,70.866 106.045,71.12 106.045,74.803 105.791,75.057 105.156,75.057 105.156,74.549 105.029,74.422 103.759,74.422 103.632,74.549 103.632,75.057
GND on Top Layer "GND_L01_P073" (solid, remove dead copper, pour order 73): 99.695,73.533 99.695,72.39 99.822,72.263 102.489,72.263 102.362,72.39 102.362,75.184 102.489,75.311
GND on Top Layer "GND_L01_P071" (solid, remove dead copper, pour order 71): 104.013,75.692 102.997,75.692 102.816,75.511 100.149,75.511 99.695,75.057 99.695,73.533 100.33,73.533 100.711,73.914 101.219,74.422 102.235,74.422 102.235,74.93 102.616,75.311 103.886,75.311
GND on Top Layer "GND_L01_P070" (solid, remove dead copper, pour order 70): 107.823,77.343 107.696,77.216 107.696,76.073 107.95,75.819 107.95,75.057 108.204,74.803 109.855,74.803 110.109,75.057 110.109,77.089 109.855,77.343
+6V on Top Layer "+6V_L01_P068" (solid, remove dead copper, pour order 68): 96.647,92.202 95.377,92.202 94.869,91.694 94.869,89.027 95.377,88.519 95.377,84.836 94.742,84.201 94.742,82.423 93.218,80.899 93.218,77.851 93.472,77.851 93.98,77.343 94.043,77.406 95.059,77.406 95.758,78.105 98.679,78.105 100.838,75.946 103.632,75.946 103.632,76.962 96.901,83.693 96.901,88.519 97.282,89.027 97.282,91.567
GND on Top Layer "GND_L01_P065" (solid, remove dead copper, pour order 65): 63.881,88.265 64.135,88.011 64.135,84.709 63.881,84.455 61.595,84.455 61.341,84.709 61.341,87.884 61.722,88.265
GND on Top Layer "GND_L01_P064" (solid, remove dead copper, pour order 64): 75.311,74.93 75.057,74.676 75.057,73.025 75.438,72.644 78.232,72.644 78.613,73.025 78.613,74.803 78.486,74.93
GND on Top Layer "GND_L01_P063" (solid, remove dead copper, pour order 63): 71.374,76.454 71.374,75.946 69.596,75.946 69.215,76.327 68.326,76.327 68.326,78.105 68.707,78.486 69.469,78.486 69.723,78.232 69.723,77.089 70.358,76.454
GND on Top Layer "GND_L01_P062" (solid, remove dead copper, pour order 62): 74.676,33.528 74.422,33.274 74.422,30.861 74.676,30.607 78.232,30.607 78.486,30.861 78.486,33.274 78.232,33.528
GND on Top Layer "GND_L01_P061" (solid, remove dead copper, pour order 61): 134.366,54.483 134.112,54.737 132.207,54.737 131.826,54.356 131.826,52.324 132.08,52.07 134.112,52.07 134.366,52.324
GND on Top Layer "GND_L01_P060" (solid, remove dead copper, pour order 60): 99.885,83.376 98.996,84.264 98.742,84.264 98.615,84.391 98.615,85.534 99.123,86.042 102.679,86.042 102.806,85.915 102.806,83.502 102.679,83.376
GND on Top Layer "GND_L01_P059" (solid, remove dead copper, pour order 59): 133.858,56.388 132.842,56.388 132.461,56.769 131.064,56.769 130.683,56.388 130.683,55.88 131.445,55.118 131.953,55.118 132.842,56.007 133.858,56.007
GND on Top Layer "GND_L01_P058" (solid, remove dead copper, pour order 58): 136.017,56.388 135.255,56.388 135.255,56.082 137.997,56.082 138.303,56.388 138.303,56.769 138.176,56.896 136.525,56.896 136.398,56.769 136.652,57.023 136.398,56.769
+5V on Top Layer "+5V_L01_P055" (solid, remove dead copper, pour order 55): 135.128,55.753 135.001,55.626 135.001,52.451 135.255,52.197 137.922,52.197 138.303,52.578 138.303,55.372 137.922,55.753
GND on Top Layer "GND_L01_P047" (solid, remove dead copper, pour order 47): 64.135,53.213 64.389,52.832 64.389,52.705 64.389,46.609 63.881,46.101 62.357,46.101 61.849,46.609 61.849,52.705 62.357,53.213
GND on Top Layer "GND_L01_P036" (solid, remove dead copper, pour order 36): 68.834,49.657 67.945,49.657 67.945,51.816 68.072,51.943 69.215,51.943 69.469,52.197 69.504,52.162 69.504,51.597 69.215,51.308 69.088,51.308 68.834,51.054 68.834,50.292
GND on Top Layer "GND_L01_P032" (solid, remove dead copper, pour order 32): 71.12,52.959 71.247,53.086 72.644,53.086 72.898,52.832 72.898,52.197 72.39,51.689 71.12,51.689
GND on Top Layer "GND_L01_P031" (solid, remove dead copper, pour order 31): 72.39,55.372 72.136,55.118 72.136,54.229 72.39,53.975 73.787,53.975 74.041,54.229 74.041,54.991 73.66,55.372
GND on Top Layer "GND_L01_P030" (solid, remove dead copper, pour order 30): 71.374,58.547 65.786,58.547 65.278,58.039 65.278,55.626 65.532,55.372 66.802,55.372 67.056,55.118 67.056,54.102 66.929,53.975 64.77,53.975 64.008,54.737 64.008,58.928 65.151,60.071 71.374,60.071 71.628,59.817 71.628,58.801
+5V on Top Layer "+5V_L01_P029" (solid, remove dead copper, pour order 29): 68.961,52.705 68.326,52.705 68.326,53.34 67.818,53.848 67.818,55.118 67.056,55.88 65.786,55.88 65.786,56.896 71.374,56.896 71.374,56.007 70.993,55.626 70.612,55.626 70.401,55.415 70.401,53.123 69.125,53.123 68.961,52.959
+6V on Top Layer "GND_bottom" (solid, pour order 17): 93.218,78.105 93.218,77.597 93.345,77.47 93.345,76.708 94.361,76.708 95.758,78.105
+5V on Top Layer "GND_bottom" (solid, pour order 14): 73.152,89.154 77.851,89.154 77.851,87.122 73.152,87.122
+5V on Top Layer "GND_bottom" (solid, pour order 9): 72.898,76.454 72.898,74.803 74.295,74.803 74.295,75.438 75.311,76.454
+5V on Top Layer "GND_bottom" (solid, pour order 8): 72.898,77.597 74.422,77.597 75.184,78.359 78.613,78.359 78.613,76.454 72.898,76.454
-5VA on Top Layer "GND_bottom" (solid, pour order 7): 64.643,76.327 67.945,76.327 67.945,78.486 64.643,78.486
-5VA on Top Layer "GND_bottom" (solid, pour order 6): 65.722,84.709 68.516,84.709 71.183,87.376 71.183,89.154 65.722,89.154
+5VA on Top Layer "GND_bottom" (solid, pour order 5): 85.09,75.692 88.519,75.692 89.549,76.722 91.61,76.722 91.61,77.427 90.424,78.613 85.09,78.613
-5VA on Bottom Layer "-5VA_L04_P066" (solid, remove dead copper, pour order 66): 66.04,86.868 68.072,86.868 68.453,86.487 68.453,84.836 67.564,83.947 66.167,83.947 65.278,83.058 65.278,79.629 66.421,78.486 67.691,78.486 67.945,78.232 67.945,76.454 67.818,76.454 67.691,76.327 65.024,76.327 64.135,77.216 64.135,83.566 65.913,85.344 65.913,86.741
+3V3 on Bottom Layer "+3V3_L04_P052" (solid, remove dead copper, pour order 52): 66.802,46.609 66.675,46.736 66.167,46.736 66.04,46.609 66.04,45.72 66.548,45.212 74.676,45.212 76.327,46.863 76.327,48.006 76.2,48.133 75.692,48.133 75.565,48.006 75.565,47.117 74.295,45.847 66.929,45.847 66.802,45.974
+3V3 on VCC (split plane): 63.371,54.229 63.38,54.179 63.408,54.137 64.267,53.279 64.309,53.251 64.358,53.241 68.594,53.241 69.984,51.851 70.026,51.823 70.075,51.814 80.438,51.814 82.732,49.519 83.321,48.93 83.363,48.902 83.413,48.893 143.508,48.893 143.508,21.209 143.509,21.193 143.5,20.992 143.472,20.776 143.425,20.564 143.36,20.357 143.276,20.156 143.176,19.963 143.059,19.78 142.927,19.607 142.78,19.447 142.62,19.3 142.447,19.168 142.264,19.051 142.071,18.951 141.87,18.867 141.663,18.802 141.451,18.755 141.235,18.727 141.034,18.718 141.018,18.719 36.322,18.719 36.306,18.718 36.105,18.727 35.889,18.755 35.677,18.802 35.47,18.867 35.269,18.951 35.076,19.051 34.893,19.168 34.72,19.3 34.56,19.447 34.413,19.607 34.281,19.78 34.164,19.963 34.064,20.156 33.98,20.357 33.915,20.564 33.868,20.776 33.84,20.992 33.831,21.193 33.832,21.209 33.832,60.118 57.454,60.118 57.503,60.128 57.545,60.156 58.601,61.212 63.371,61.212
-5VA on VCC (split plane): 36.322,95.699 72.134,95.699 72.134,88.519 72.134,80.264 72.143,80.214 72.171,80.172 72.769,79.575 72.769,78.413 72.171,77.816 72.143,77.774 72.134,77.724 72.134,74.603 70.593,73.062 33.832,73.062 33.832,93.209 33.831,93.225 33.84,93.426 33.868,93.642 33.915,93.854 33.98,94.061 34.064,94.262 34.164,94.455 34.281,94.638 34.413,94.811 34.56,94.971 34.72,95.118 34.893,95.25 35.076,95.367 35.269,95.467 35.47,95.551 35.677,95.616 35.889,95.663 36.105,95.691 36.306,95.7
+5V on VCC (split plane): 141.235,95.691 141.451,95.663 141.663,95.616 141.87,95.551 142.071,95.467 142.264,95.367 142.447,95.25 142.62,95.118 142.78,94.971 142.927,94.811 143.059,94.638 143.176,94.455 143.276,94.262 143.36,94.061 143.425,93.854 143.472,93.642 143.5,93.426 143.509,93.225 143.508,93.209 143.508,49.151 83.466,49.151 82.915,49.703 80.583,52.035 80.541,52.063 80.492,52.072 70.129,52.072 68.739,53.462 68.697,53.49 68.648,53.5 64.412,53.5 63.629,54.283 63.629,61.212 78.232,61.212 78.282,61.221 78.324,61.249 87.303,70.229 89.662,70.229 89.712,70.238 89.754,70.266 91.786,72.298 91.814,72.34 91.823,72.39 91.823,78.613 91.814,78.663 91.786,78.705 90.262,80.229 90.22,80.257 90.17,80.266 83.312,80.266 83.262,80.257 83.22,80.229 81.061,78.07 81.033,78.028 81.024,77.978 81.024,72.825 77.632,69.434 73.676,65.477 33.832,65.477 33.832,72.803 70.646,72.803 70.696,72.813 70.738,72.841 72.355,74.457 72.383,74.499 72.392,74.549 72.392,77.67 72.99,78.267 73.018,78.309 73.027,78.359 73.027,79.629 73.018,79.679 72.99,79.721 72.392,80.318 72.392,88.519 72.392,95.699 141.018,95.699 141.034,95.7
+5VA on VCC (split plane): 91.565,78.559 91.565,72.444 89.608,70.487 87.249,70.487 87.199,70.478 87.157,70.45 78.178,61.47 58.547,61.47 58.497,61.461 58.455,61.433 57.4,60.377 33.832,60.377 33.832,65.218 73.73,65.218 73.779,65.228 73.821,65.256 77.816,69.25 81.245,72.679 81.273,72.721 81.282,72.771 81.282,77.924 83.366,80.008 90.116,80.008
GND on GND (split plane): 141.235,95.691 141.451,95.663 141.663,95.616 141.87,95.551 142.071,95.467 142.264,95.367 142.447,95.25 142.62,95.118 142.78,94.971 142.927,94.811 143.059,94.638 143.176,94.455 143.276,94.262 143.36,94.061 143.425,93.854 143.472,93.642 143.5,93.426 143.509,93.225 143.508,93.209 143.508,21.209 143.509,21.193 143.5,20.992 143.472,20.776 143.425,20.564 143.36,20.357 143.276,20.156 143.176,19.963 143.059,19.78 142.927,19.607 142.78,19.447 142.62,19.3 142.447,19.168 142.264,19.051 142.071,18.951 141.87,18.867 141.663,18.802 141.451,18.755 141.235,18.727 141.034,18.718 141.018,18.719 36.322,18.719 36.306,18.718 36.105,18.727 35.889,18.755 35.677,18.802 35.47,18.867 35.269,18.951 35.076,19.051 34.893,19.168 34.72,19.3 34.56,19.447 34.413,19.607 34.281,19.78 34.164,19.963 34.064,20.156 33.98,20.357 33.915,20.564 33.868,20.776 33.84,20.992 33.831,21.193 33.832,21.209 33.832,93.209 33.831,93.225 33.84,93.426 33.868,93.642 33.915,93.854 33.98,94.061 34.064,94.262 34.164,94.455 34.281,94.638 34.413,94.811 34.56,94.971 34.72,95.118 34.893,95.25 35.076,95.367 35.269,95.467 35.47,95.551 35.677,95.616 35.889,95.663 36.105,95.691 36.306,95.7 36.322,95.699 141.018,95.699 141.034,95.7

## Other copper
VCC (plane layer: these items are gaps in the copper):
  lines w0.254: 33.02,65.348 73.73,65.348 77.724,69.342 81.153,72.771 81.153,77.978 83.312,80.137 89.789,80.137 90.17,80.137 91.694,78.613 91.694,72.39 89.662,70.358 87.249,70.358 78.232,61.341 58.547,61.341 57.454,60.248 33.147,60.248 ; 33.274,72.932 70.646,72.932 72.263,74.549 72.263,77.724 72.898,78.359 72.898,79.629 72.263,80.264 72.263,88.519 72.263,96.266 ; 63.5,61.214 63.5,54.229 64.358,53.371 68.648,53.371 70.075,51.943 80.492,51.943 82.824,49.611 83.413,49.022 144.018,49.022

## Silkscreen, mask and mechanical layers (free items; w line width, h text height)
Top Overlay:
  drawing of 3721 lines, arcs and shapes, not listed
Mechanical 1:
  the board outline again, w1.016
